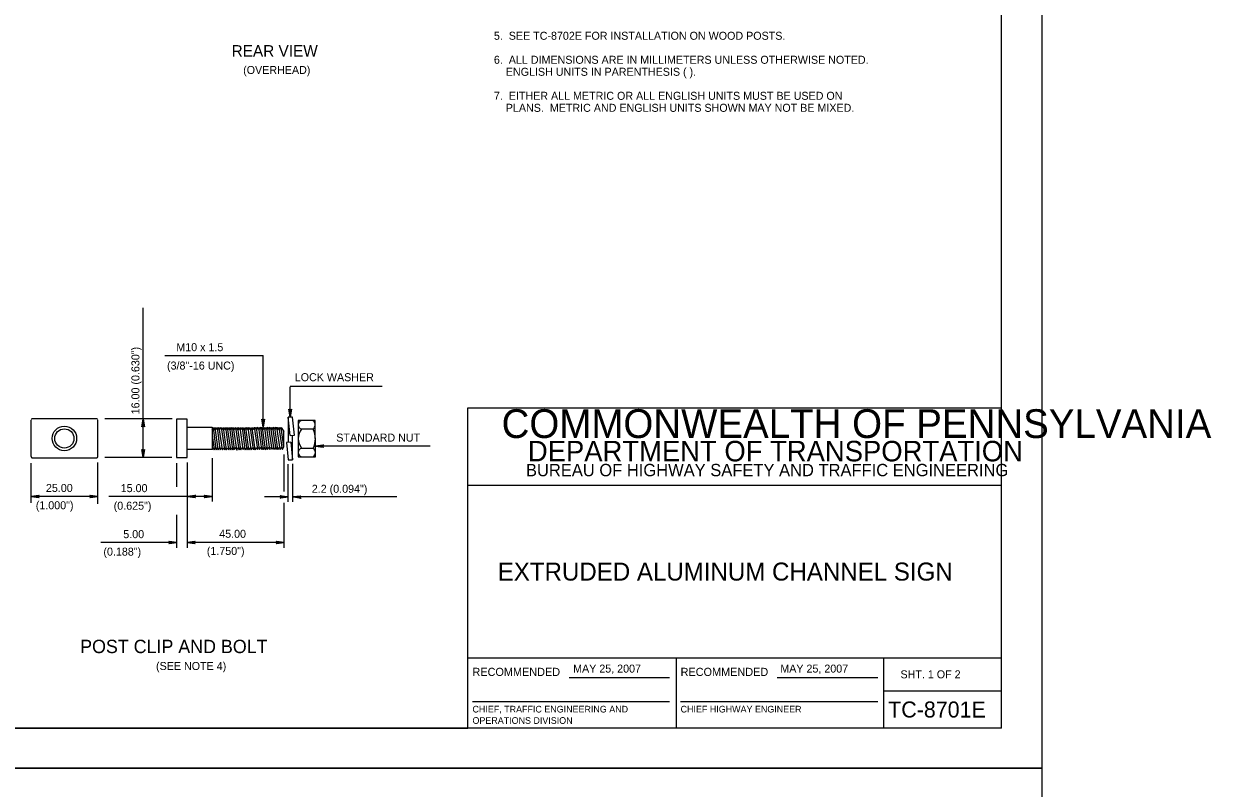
# Model space of a CAD drawing. Extents: x 647822 to 648727, y 298458 to 299646.
# Drawn here: x 648281.8 to 648726.9, y 299044.1 to 299330.6 of the extents above; entities that cross this region are included whole.
import ezdxf

# ---------------------------------------------------------------- set-up
doc = ezdxf.new("R2010")
doc.units = 0
for name, color, linetype in [('1', 7, 'Continuous'), ('2', 7, 'Continuous'), ('3', 7, 'Continuous'), ('XCS-GRID-MIN', 7, 'Continuous')]:
    doc.layers.add(name, color=color, linetype=linetype)

# ---------------------------------------------------------------- blocks, each defined once
blk = doc.blocks.new('RARROW')
at = {"layer": '3'}
blk.add_lwpolyline([(-2.2695, 0.285), (-2.184875, 0.12075), (0, 0), (-2.2695, 0.285), (-2.38575, 0.384625), (0, 0), (-2.183125, -0.108), (-2.262875, -0.2705), (0, 0), (-2.38575, -0.379125), (-2.262875, -0.2705)], dxfattribs=at)

msp = doc.modelspace()

# ---------------------------------------------------------------- linework, layer by layer
at = {"layer": '1'}
for p, q in [((648648.31, 299066.63), (648648.31, 299630.63)), ((648448.31, 299066.63), (648448.31, 299186.63)), ((648448.31, 299186.63), (648648.31, 299186.63)), ((648648.31, 299157.63), (648448.31, 299157.63)), ((648448.31, 299093), (648648.31, 299093)), ((648526.31, 299093), (648526.31, 299066.63)), ((648604.19, 299066.63), (648604.19, 299093)), ((648486.24, 299085.57), (648523.87, 299085.57)), ((648564.24, 299085.57), (648601.87, 299085.57)), ((648604.19, 299080.63), (648648.31, 299080.63)), ((648449.99, 299076.68), (648523.87, 299076.68)), ((648527.99, 299076.68), (648601.87, 299076.68)), ((648648.31, 299066.63), (647862.31, 299066.63)), ((647862.31, 299066.63), (648448.31, 299066.63))]:
    msp.add_line(p, q, dxfattribs=at)
at = {"layer": '2'}
for p, q in [((648326.55, 299168.07), (648326.55, 299224.2)), ((648334.7, 299206.34), (648371.53, 299206.34)), ((648371.53, 299179.44), (648371.53, 299206.34)), ((648416.12, 299194.69), (648381.71, 299194.69)), ((648381.71, 299183.19), (648381.71, 299194.57)), ((648284.53, 299182.07), (648284.53, 299168.44)), ((648309.15, 299182.57), (648284.9, 299182.57)), ((648309.53, 299168.44), (648309.53, 299182.07)), ((648337.4, 299182.57), (648312.15, 299182.57)), ((648339.03, 299182.44), (648339.03, 299168.07)), ((648343.03, 299182.44), (648339.03, 299182.44)), ((648343.03, 299168.07), (648343.03, 299182.44)), ((648382.58, 299183.19), (648380.96, 299183.19)), ((648381.64, 299176.29), (648380.96, 299183.19)), ((648380.96, 299183.19), (648380.96, 299173.68)), ((648383.25, 299176.45), (648382.58, 299183.19)), ((648384.65, 299181.94), (648384.65, 299168.32)), ((648391, 299181.94), (648384.65, 299181.94)), ((648391.17, 299168.32), (648391, 299181.94)), ((648343.03, 299179.44), (648352.46, 299179.44)), ((648352.46, 299179.44), (648352.46, 299171.07)), ((648352.46, 299179.44), (648352.46, 299171.07)), ((648352.46, 299178.57), (648352.88, 299179.32)), ((648352.46, 299176.32), (648353.15, 299171.07)), ((648353.98, 299171.07), (648352.88, 299179.32)), ((648352.88, 299179.32), (648353.15, 299178.57)), ((648353.15, 299178.57), (648353.56, 299179.32)), ((648354.66, 299171.07), (648353.56, 299179.32)), ((648353.56, 299179.32), (648353.98, 299178.57)), ((648353.98, 299178.57), (648354.39, 299179.44)), ((648354.39, 299179.44), (648354.8, 299178.57)), ((648355.49, 299171.07), (648354.39, 299179.32)), ((648354.8, 299178.57), (648355.21, 299179.32)), ((648356.31, 299171.07), (648355.08, 299179.32)), ((648355.21, 299179.32), (648355.49, 299178.69)), ((648355.49, 299178.69), (648355.9, 299179.32)), ((648357.14, 299171.07), (648355.9, 299179.32)), ((648355.9, 299179.32), (648356.31, 299178.57)), ((648356.31, 299178.57), (648356.73, 299179.32)), ((648357.83, 299171.07), (648356.73, 299179.32)), ((648356.73, 299179.32), (648357.14, 299178.57)), ((648357.14, 299178.57), (648357.55, 299179.32)), ((648358.65, 299171.07), (648357.55, 299179.32)), ((648357.55, 299179.32), (648357.96, 299178.57)), ((648357.96, 299178.57), (648358.24, 299179.32)), ((648359.48, 299171.07), (648358.24, 299179.32)), ((648358.24, 299179.32), (648358.65, 299178.57)), ((648358.65, 299178.57), (648359.06, 299179.32)), ((648360.16, 299171.07), (648359.06, 299179.32)), ((648359.06, 299179.32), (648359.34, 299178.57)), ((648359.34, 299178.57), (648359.75, 299179.32)), ((648360.85, 299171.07), (648359.75, 299179.32)), ((648359.75, 299179.32), (648360.16, 299178.57)), ((648360.16, 299178.57), (648360.44, 299179.32)), ((648361.68, 299171.07), (648360.44, 299179.32)), ((648360.44, 299179.32), (648360.85, 299178.57)), ((648360.85, 299178.57), (648361.26, 299179.32)), ((648362.5, 299171.07), (648361.26, 299179.32)), ((648361.26, 299179.32), (648361.68, 299178.57)), ((648361.68, 299178.57), (648362.09, 299179.32)), ((648363.19, 299171.07), (648362.09, 299179.32)), ((648362.09, 299179.32), (648362.5, 299178.57)), ((648362.5, 299178.57), (648362.91, 299179.32)), ((648364.01, 299171.07), (648362.91, 299179.32)), ((648362.91, 299179.32), (648363.33, 299178.57)), ((648363.33, 299178.57), (648363.74, 299179.32)), ((648364.84, 299171.07), (648363.74, 299179.32)), ((648363.74, 299179.32), (648364.01, 299178.57)), ((648364.01, 299178.57), (648364.43, 299179.32)), ((648364.43, 299179.32), (648364.84, 299178.57)), ((648365.53, 299170.94), (648364.43, 299179.19)), ((648364.84, 299178.57), (648365.11, 299179.32)), ((648366.21, 299171.07), (648365.11, 299179.32)), ((648365.11, 299179.32), (648365.66, 299178.57)), ((648365.66, 299178.57), (648365.94, 299179.44)), ((648365.94, 299179.44), (648366.35, 299178.57)), ((648367.04, 299171.07), (648365.94, 299179.32)), ((648366.35, 299178.57), (648366.76, 299179.32)), ((648366.76, 299179.32), (648367.04, 299178.57)), ((648367.86, 299170.94), (648366.76, 299179.19)), ((648367.04, 299178.57), (648367.45, 299179.32)), ((648367.45, 299179.32), (648367.86, 299178.57)), ((648368.55, 299170.94), (648367.45, 299179.19)), ((648367.86, 299178.57), (648368.28, 299179.32)), ((648368.14, 299178.94), (648368.28, 299179.44)), ((648369.51, 299171.19), (648368.28, 299179.44)), ((648368.28, 299179.44), (648368.69, 299178.69)), ((648368.69, 299178.69), (648369.1, 299179.44)), ((648368.69, 299178.69), (648369.1, 299179.44)), ((648369.1, 299179.44), (648369.51, 299178.69)), ((648370.2, 299171.07), (648369.1, 299179.32)), ((648369.51, 299178.69), (648369.79, 299179.44)), ((648369.79, 299179.44), (648370.2, 299178.69)), ((648371.03, 299171.07), (648369.93, 299179.32)), ((648370.2, 299178.69), (648370.61, 299179.44)), ((648371.71, 299171.19), (648370.61, 299179.44)), ((648370.61, 299179.44), (648371.03, 299178.57)), ((648371.03, 299178.57), (648371.3, 299179.44)), ((648371.3, 299179.44), (648371.71, 299178.57)), ((648372.4, 299170.94), (648371.3, 299179.32)), ((648371.71, 299178.57), (648372.13, 299179.44)), ((648372.13, 299179.44), (648372.54, 299178.69)), ((648373.23, 299171.07), (648372.13, 299179.32)), ((648372.54, 299178.69), (648372.95, 299179.44)), ((648372.95, 299179.44), (648373.36, 299178.69)), ((648374.05, 299171.07), (648372.95, 299179.32)), ((648373.36, 299178.69), (648373.64, 299179.44)), ((648373.64, 299179.44), (648374.19, 299178.69)), ((648374.88, 299171.07), (648373.64, 299179.32)), ((648374.19, 299178.69), (648374.46, 299179.44)), ((648374.46, 299179.44), (648374.88, 299178.57)), ((648375.7, 299171.07), (648374.46, 299179.32)), ((648374.88, 299178.57), (648375.15, 299179.44)), ((648375.15, 299179.44), (648375.7, 299178.69)), ((648376.39, 299171.07), (648375.15, 299179.32)), ((648375.7, 299178.69), (648375.98, 299179.44)), ((648375.98, 299179.44), (648376.39, 299178.69)), ((648377.08, 299171.07), (648375.98, 299179.32)), ((648376.39, 299178.69), (648376.8, 299179.44)), ((648377.9, 299171.19), (648376.66, 299179.44)), ((648376.8, 299179.44), (648377.21, 299178.57)), ((648377.21, 299178.57), (648377.49, 299179.44)), ((648377.49, 299179.44), (648377.9, 299178.69)), ((648378.73, 299171.07), (648377.49, 299179.32)), ((648377.9, 299178.69), (648378.31, 299179.32)), ((648378.31, 299179.32), (648379.28, 299177.82)), ((648379.28, 299172.07), (648378.31, 299179.32)), ((648379.28, 299171.94), (648379.28, 299177.82)), ((648381.64, 299176.29), (648383.25, 299176.45)), ((648382.58, 299167.19), (648382.58, 299176.45)), ((648390.4, 299178.69), (648385.9, 299178.69)), ((648381.94, 299173.84), (648380.33, 299173.68)), ((648380.33, 299173.68), (648380.96, 299167.19)), ((648381.94, 299173.84), (648382.58, 299167.19)), ((648390.28, 299171.44), (648385.9, 299171.44)), ((648434.08, 299172.32), (648391.12, 299172.32)), ((648284.9, 299167.94), (648309.15, 299167.94)), ((648337.28, 299168.07), (648312.15, 299168.07)), ((648339.03, 299168.07), (648343.03, 299168.07)), ((648352.46, 299171.07), (648343.03, 299171.07)), ((648344.4, 299170.94), (648344.4, 299170.94)), ((648352.46, 299167.77), (648352.46, 299151.6)), ((648353.29, 299170.94), (648353.29, 299171.07)), ((648379.4, 299155.27), (648379.4, 299169.19)), ((648380.96, 299167.19), (648382.58, 299167.19)), ((648384.65, 299168.32), (648391.17, 299168.32)), ((648391.15, 299169.82), (648391.03, 299169.82)), ((648284.65, 299151.02), (648284.65, 299165.94)), ((648309.53, 299150.74), (648309.53, 299166.19)), ((648339.15, 299157.1), (648339.15, 299165.97)), ((648343.15, 299134.23), (648343.15, 299166.19)), ((648380.96, 299151.39), (648380.96, 299165.57)), ((648382.71, 299151.51), (648382.71, 299165.69)), ((648309.53, 299153.42), (648284.65, 299153.42)), ((648352.46, 299153.42), (648313.74, 299153.42)), ((648352.46, 299153.42), (648343.03, 299153.42)), ((648380.96, 299153.26), (648372.01, 299153.26)), ((648379.4, 299134.23), (648379.4, 299151.12)), ((648421.63, 299153.26), (648382.71, 299153.26)), ((648339.15, 299134.23), (648339.15, 299146.57)), ((648339.15, 299136.23), (648310.66, 299136.23)), ((648379.4, 299136.23), (648343.03, 299136.23))]:
    msp.add_line(p, q, dxfattribs=at)
for points in [[(648352.46, 299171.07), (648352.74, 299171.82), (648353.15, 299170.94), (648353.56, 299171.82), (648353.98, 299170.94), (648354.39, 299171.82), (648354.66, 299170.94), (648355.08, 299171.69), (648355.49, 299170.94), (648355.9, 299171.69), (648356.31, 299170.94), (648356.59, 299171.69), (648357.14, 299170.94), (648357.41, 299171.82), (648357.83, 299170.94), (648358.24, 299171.69), (648358.65, 299170.94), (648358.93, 299171.82), (648359.48, 299170.94), (648359.75, 299171.69), (648360.16, 299170.94), (648360.58, 299171.82), (648360.85, 299171.07), (648361.26, 299171.82), (648361.68, 299170.82), (648362.09, 299171.82), (648362.5, 299170.94), (648362.78, 299171.82), (648363.19, 299170.94), (648363.6, 299171.82), (648364.01, 299171.07), (648364.43, 299171.69), (648364.84, 299170.94), (648365.11, 299171.69), (648365.53, 299170.94), (648365.94, 299171.82), (648366.21, 299170.94), (648366.76, 299171.69), (648367.04, 299170.94), (648367.45, 299171.82), (648367.86, 299171.07), (648368.28, 299171.69), (648368.55, 299170.94), (648368.96, 299171.82), (648369.24, 299171.19)], [(648369.1, 299171.69), (648369.38, 299171.07), (648369.79, 299171.94), (648370.2, 299171.07), (648370.61, 299171.82), (648371.03, 299171.07), (648371.3, 299171.94), (648371.71, 299171.07), (648372.13, 299171.94), (648372.4, 299170.94), (648372.95, 299171.94), (648373.23, 299171.07), (648373.64, 299171.94), (648374.05, 299171.07), (648374.33, 299171.94), (648374.88, 299171.19), (648375.15, 299171.82), (648375.7, 299171.07), (648375.98, 299171.82), (648376.39, 299171.07), (648376.66, 299171.94), (648377.08, 299171.07), (648377.63, 299171.82), (648377.9, 299171.07), (648378.18, 299171.94), (648378.73, 299171.07), (648379.28, 299172.07)]]:
    msp.add_lwpolyline(points, dxfattribs=at)
for radius in [4.6, 3.6]:
    msp.add_circle((648297.05, 299175.21), radius, dxfattribs=at)
for centre, radius, start, end in [((648386.36, 299180.31), 1.66, 104.9492, 255.0508), ((648388.97, 299180.27), 2.06, 310.6013, 49.3987), ((648390.48, 299175.14), 5.78, 141.8914, 218.1086), ((648382.49, 299175.09), 8.62, 335.1961, 24.8039), ((648386.31, 299169.9), 1.61, 103.5194, 256.4806), ((648389.14, 299169.92), 1.97, 305.7161, 54.2839)]:
    msp.add_arc(centre, radius, start, end, dxfattribs=at)
for centre, major_axis, start_param, end_param in [((648284.94, 299182.12), (0, 0.456), 0, 1.570796), ((648309.18, 299182.12), (0, 0.456), 4.712389, 6.283185), ((648284.94, 299168.41), (0, -0.456), 4.712389, 6.283185), ((648309.18, 299168.41), (0, -0.456), 0, 1.570796)]:
    msp.add_ellipse(centre, major_axis=major_axis, ratio=0.833333, start_param=start_param, end_param=end_param, dxfattribs=at)
at = {"layer": 'XCS-GRID-MIN'}
for points in [[(647822.31, 299645.63), (648663.31, 299645.63), (648663.31, 299051.63), (647822.31, 299051.63)], [(647822.31, 299051.63), (648663.31, 299051.63), (648663.31, 298457.63), (647822.31, 298457.63)]]:
    msp.add_lwpolyline(points, close=True, dxfattribs=at)

# ---------------------------------------------------------------- block references
at = {"layer": '2', "xscale": 1.2574347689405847, "yscale": 1.3092961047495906}
for p, rotation in [((648381.71, 299183.19), -90.00000000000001), ((648326.55, 299182.57), 89.99999999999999), ((648371.53, 299179.44), -90.00000000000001), ((648391.12, 299172.32), 180), ((648326.55, 299168.07), -90.00000000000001), ((648284.65, 299153.42), 180), ((648343.15, 299153.42), 180), ((648382.71, 299153.26), 180), ((648343.03, 299136.23), 180)]:
    msp.add_blockref('RARROW', p, dxfattribs=dict(at, rotation=rotation))
for p in [(648309.53, 299153.42), (648352.46, 299153.42), (648380.96, 299153.26), (648339.15, 299136.23), (648379.4, 299136.23)]:
    msp.add_blockref('RARROW', p, dxfattribs=at)

# ---------------------------------------------------------------- texts
at = {"layer": '1'}
for s, height, p in [('COMMONWEALTH OF PENNSYLVANIA', 10.7828, (648460.9, 299175.36)), ('DEPARTMENT OF TRANSPORTATION', 7.6837, (648470.76, 299166.61)), ('BUREAU OF HIGHWAY SAFETY AND TRAFFIC ENGINEERING', 4.6253, (648470.04, 299161.04)), ('EXTRUDED ALUMINUM CHANNEL SIGN', 6.75, (648459.45, 299121.94)), ('RECOMMENDED', 3.048, (648449.99, 299086.2)), ('RECOMMENDED', 3.048, (648527.99, 299086.2)), ('SHT. 1 OF 2', 3, (648610.4, 299085.31)), ('CHIEF, TRAFFIC ENGINEERING AND', 2.5, (648449.99, 299072.51)), ('CHIEF HIGHWAY ENGINEER', 2.5, (648527.99, 299072.51)), ('TC-8701E', 6, (648605.79, 299070.63)), ('OPERATIONS DIVISION', 2.5, (648449.99, 299068.26))]:
    msp.add_text(s, height=height, dxfattribs=at).set_placement(p)
at = {"layer": '2'}
for s, height, p in [('5.  SEE TC-8702E FOR INSTALLATION ON WOOD POSTS.', 3, (648458.02, 299324.59)), ('REAR VIEW', 4.3, (648359.73, 299318.27)), ('6.  ALL DIMENSIONS ARE IN MILLIMETERS UNLESS OTHERWISE NOTED.', 3, (648458.02, 299315.59)), ('(OVERHEAD)', 3, (648364.05, 299311.77)), ('    ENGLISH UNITS IN PARENTHESIS ( ).', 3, (648458.02, 299311.09)), ('7.  EITHER ALL METRIC OR ALL ENGLISH UNITS MUST BE USED ON', 3, (648458.02, 299302.09)), ('    PLANS.  METRIC AND ENGLISH UNITS SHOWN MAY NOT BE MIXED.', 3, (648458.02, 299297.59)), (' M10 x 1.5 ', 3, (648337.88, 299207.9)), ('(3/8"-16 UNC)', 3, (648335.51, 299201.01)), ('LOCK WASHER', 3, (648383.39, 299196.65)), ('STANDARD NUT', 3, (648398.94, 299174.02)), ('25.00', 3, (648290.13, 299155.15)), ('15.00', 3, (648318.16, 299155.08)), ('2.2 (0.094")', 3, (648389.77, 299154.84)), ('(1.000")', 3, (648286.33, 299148.67)), ('(0.625")', 3, (648315.53, 299148.49)), ('5.00', 3, (648319.12, 299137.84)), ('45.00', 3, (648355.07, 299137.98)), ('(0.188")', 3, (648311.68, 299131.29)), ('(1.750")', 3, (648350.43, 299131.55)), ('POST CLIP AND BOLT', 5, (648302.96, 299094.76)), ('(SEE NOTE 4)', 3, (648331.4, 299088.44)), ('MAY 25, 2007', 3, (648487.71, 299087.46)), ('MAY 25, 2007', 3, (648565.36, 299087.46))]:
    msp.add_text(s, height=height, dxfattribs=at).set_placement(p)
msp.add_text('16.00 (0.630")', height=3, rotation=90, dxfattribs=at).set_placement((648325.17, 299184.23))

doc.saveas('drawing.dxf')
